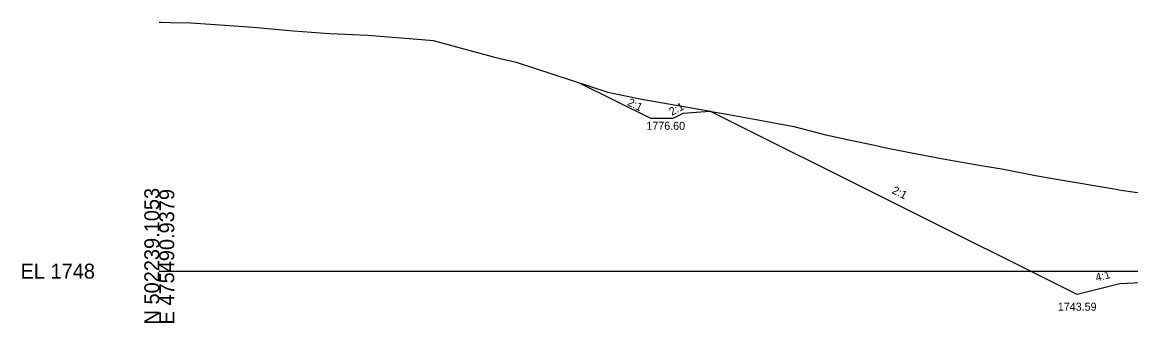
# Model space of a CAD drawing. Extents: x -26 to 1803, y -10 to 9558.
# Drawn here: x -25.7 to 182.1, y 8490.3 to 8546.7 of the extents above; entities that cross this region are included whole.
import ezdxf

# ---------------------------------------------------------------- set-up
doc = ezdxf.new("R2010")
doc.units = 0
for name, color, linetype in [('Exist Cross Section Cell', 7, 'Continuous'), ('Exist XS Ground Line', 7, 'Continuous'), ('Prop XS DDE', 7, 'Continuous'), ('Prop XS Ditch Slope Text', 7, 'Continuous'), ('Prop XS Ditch Standard Text', 7, 'Continuous'), ('Prop XS Dump Level', 7, 'Continuous'), ('Prop XS Earthwork Shape', 7, 'Continuous'), ('Prop XS Finish Grade Earthwork', 7, 'Continuous'), ('Prop XS Hydro Typical Ditch Data', 7, 'Continuous'), ('Prop XS Side Slope Text', 7, 'Continuous')]:
    doc.layers.add(name, color=color, linetype=linetype)

msp = doc.modelspace()

# ---------------------------------------------------------------- linework, layer by layer
at = {"layer": 'Exist Cross Section Cell'}
msp.add_line((0, 8500), (200, 8500), dxfattribs=at)
at = {"layer": 'Exist XS Ground Line'}
msp.add_lwpolyline([(0, 8546.68), (0.31, 8546.68), (2.07, 8546.64), (5.93, 8546.55), (9.61, 8546.31), (17.57, 8545.76), (25.17, 8545.06), (31.87, 8544.57), (39.06, 8544.23), (47.55, 8543.56), (49.21, 8543.46), (51.33, 8543.24), (63.07, 8540.05), (66.89, 8539.21), (84.08, 8533.58), (87.36, 8532.84), (90.42, 8532.24), (102.95, 8530.06), (103.8, 8529.9), (105.67, 8529.53), (113.93, 8528.08), (118.91, 8527.13), (124.92, 8525.56), (129.86, 8524.52), (134.01, 8523.6), (135.9, 8523.17), (140.94, 8522.19), (146.89, 8521.04), (154.04, 8519.82), (156.68, 8519.39), (157.87, 8519.17), (164.23, 8517.93), (168.86, 8517.09), (178.22, 8515.53), (179.34, 8515.35), (179.84, 8515.27), (186.89, 8514.25)], dxfattribs=at)
at = {"layer": 'Prop XS DDE'}
for p, q in [((78.59, 8535.38), (92.15, 8528.6)), ((96.15, 8528.6), (92.15, 8528.6)), ((96.15, 8528.6), (98.15, 8529.6)), ((98.15, 8529.6), (103.15, 8530.02))]:
    msp.add_line(p, q, dxfattribs=at)
at = {"layer": 'Prop XS Earthwork Shape'}
msp.add_lwpolyline([(183.98, 8497.79), (180, 8497.59), (172, 8495.59), (103.15, 8530.02), (103.8, 8529.9), (105.67, 8529.53), (113.93, 8528.08), (118.91, 8527.13), (124.92, 8525.56), (129.86, 8524.52), (134.01, 8523.6), (135.9, 8523.17), (140.94, 8522.19), (146.89, 8521.04), (154.04, 8519.82), (156.68, 8519.39), (157.87, 8519.17), (164.23, 8517.93), (168.86, 8517.09), (178.22, 8515.53), (179.34, 8515.35), (179.84, 8515.27), (186.89, 8514.25)], dxfattribs=at)
at = {"layer": 'Prop XS Finish Grade Earthwork'}
for p, q in [((172, 8495.59), (103.15, 8530.02)), ((180, 8497.59), (172, 8495.59)), ((183.98, 8497.79), (180, 8497.59))]:
    msp.add_line(p, q, dxfattribs=at)
at = {"layer": 'Prop XS Hydro Typical Ditch Data'}
for p, q in [((172, 8495.59), (103.15, 8530.02)), ((180, 8497.59), (172, 8495.59))]:
    msp.add_line(p, q, dxfattribs=at)

# ---------------------------------------------------------------- texts
at = {"layer": 'Exist Cross Section Cell'}
for s, p in [('N 502239.1053', (0, 8490)), ('E 475490.9379', (2.8, 8490))]:
    msp.add_text(s, height=2.8, rotation=90, dxfattribs=at).set_placement(p)
msp.add_text('EL 1748', height=2.8, dxfattribs=at).set_placement((-26, 8498.6))
at = {"layer": 'Prop XS Ditch Slope Text'}
msp.add_text('4:1', height=1.5, rotation=14.0362, dxfattribs=at).set_placement((175.64, 8498.05))
at = {"layer": 'Prop XS Ditch Standard Text'}
for s, p in [('1776.60', (91.28, 8526.5)), ('1743.59', (168.39, 8492.59))]:
    msp.add_text(s, height=1.5, dxfattribs=at).set_placement(p)
at = {"layer": 'Prop XS Dump Level'}
msp.add_text('Case1', height=0.04, dxfattribs=at).set_placement((180, 8497.55))
at = {"layer": 'Prop XS Side Slope Text'}
for rotation, p in [(333.4349, (87.6, 8531.19)), (28.5444, (96.05, 8529.1)), (333.4349, (137.18, 8514.68))]:
    msp.add_text('2:1', height=1.5, rotation=rotation, dxfattribs=at).set_placement(p)

doc.saveas('drawing.dxf')
